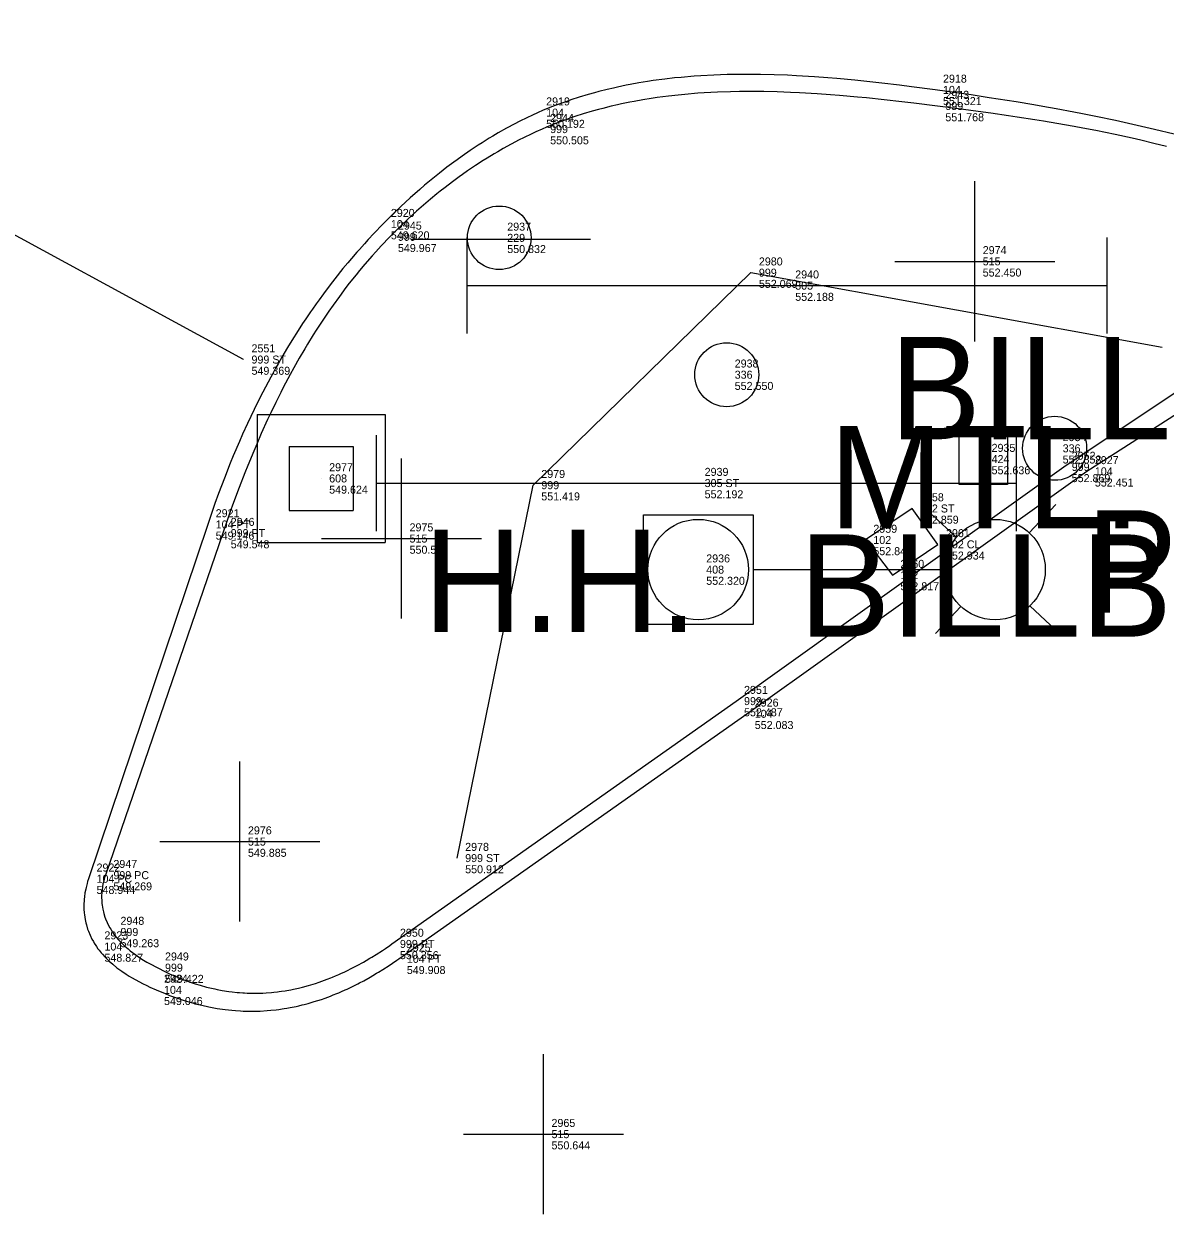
# Model space of a CAD drawing. Extents: x 5447 to 709667, y 4528 to 375505.
# Drawn here: x 708143.16 to 708178.82, y 374179.62 to 374216.81 of the extents above; entities that cross this region are included whole.
import ezdxf

# ---------------------------------------------------------------- set-up
doc = ezdxf.new("R2010")
doc.units = 0
for name, color, linetype in [('SV_BKLN_BKLN', 7, 'Continuous'), ('SV_ILUM_LUMINAIRE_STANDARD', 7, 'Continuous'), ('SV_NODES_ACTIVE_POINT', 7, 'Continuous'), ('SV_NODES_DESCRIPTION', 7, 'Continuous'), ('SV_NODES_ELEVATION', 7, 'Continuous'), ('SV_NODES_PT_NUMBER', 7, 'Continuous'), ('SV_ROAD_BCURB', 7, 'Continuous'), ('SV_ROAD_CONCRD', 7, 'Continuous'), ('SV_SIGN_BB', 7, 'Continuous'), ('SV_SIGN_BB_TX', 7, 'Continuous'), ('SV_SIGN_MISC_SIGN_POST', 7, 'Continuous'), ('SV_SIGN_SIGN', 7, 'Continuous'), ('SV_SIGN_SIGN_TX', 7, 'Continuous'), ('SV_SURF_SPOT', 7, 'Continuous'), ('SV_TRAF_HH', 7, 'Continuous'), ('SV_TRAF_TRAF_TX', 7, 'Continuous'), ('SV_UTOH_MISC_OH', 7, 'Continuous'), ('SV_UTOH_UTOH_TX', 7, 'Continuous')]:
    doc.layers.add(name, color=color, linetype=linetype)

msp = doc.modelspace()

# ---------------------------------------------------------------- linework, layer by layer
at = {"layer": 'SV_BKLN_BKLN'}
for points in [[(708150.021, 374206.324), (708130.411, 374216.99), (708111.595, 374232.817)], [(708178.866, 374212.98), (708178.466, 374213.08), (708178.065, 374213.176), (708177.797, 374213.237), (708177.26, 374213.355), (708176.653, 374213.479), (708176.248, 374213.557), (708175.976, 374213.607), (708175.433, 374213.704), (708175.023, 374213.773), (708174.75, 374213.817), (708174.201, 374213.903), (708173.926, 374213.944), (708173.374, 374214.023), (708172.82, 374214.1), (708172.449, 374214.149), (708171.704, 374214.245), (708170.967, 374214.336), (708170.598, 374214.379), (708170.042, 374214.442), (708169.485, 374214.499), (708169.206, 374214.526), (708168.648, 374214.576), (708168.369, 374214.598), (708167.951, 374214.628), (708167.393, 374214.66), (708167.114, 374214.673), (708166.697, 374214.688), (708166.281, 374214.697), (708166.073, 374214.699), (708165.704, 374214.699), (708165.52, 374214.698), (708165.244, 374214.692), (708164.832, 374214.678), (708164.421, 374214.656), (708164.216, 374214.643), (708163.808, 374214.609), (708163.605, 374214.589), (708163.301, 374214.555), (708162.943, 374214.508), (708162.764, 374214.481), (708162.497, 374214.438), (708162.231, 374214.391), (708162.099, 374214.365), (708161.835, 374214.311), (708161.704, 374214.282), (708161.507, 374214.237), (708161.246, 374214.172), (708161.116, 374214.137), (708160.922, 374214.084), (708160.632, 374213.997), (708160.377, 374213.915), (708160.249, 374213.872), (708160.059, 374213.805), (708159.775, 374213.699), (708159.494, 374213.585), (708159.354, 374213.525), (708159.158, 374213.438), (708159.027, 374213.378), (708158.768, 374213.253), (708158.64, 374213.188), (708158.384, 374213.054), (708158.131, 374212.914), (708157.964, 374212.818), (708157.853, 374212.753), (708157.632, 374212.618), (708157.509, 374212.541), (708157.266, 374212.383), (708157.025, 374212.219), (708156.866, 374212.108), (708156.761, 374212.032), (708156.552, 374211.879), (708156.321, 374211.702), (708156.168, 374211.582), (708156.067, 374211.501), (708155.868, 374211.337), (708155.72, 374211.212), (708155.429, 374210.957), (708155.144, 374210.696), (708154.959, 374210.519), (708154.837, 374210.4), (708154.597, 374210.159), (708154.328, 374209.878), (708154.153, 374209.688), (708154.039, 374209.56), (708153.814, 374209.301), (708153.648, 374209.105), (708153.54, 374208.973), (708153.327, 374208.706), (708153.223, 374208.571), (708153.018, 374208.299), (708152.818, 374208.023), (708152.688, 374207.837), (708152.602, 374207.712), (708152.433, 374207.46), (708152.294, 374207.245), (708152.202, 374207.101), (708152.022, 374206.809), (708151.934, 374206.662), (708151.76, 374206.365), (708151.591, 374206.063), (708151.48, 374205.861), (708151.407, 374205.724), (708151.263, 374205.45), (708151.184, 374205.294), (708151.027, 374204.979), (708150.874, 374204.661), (708150.774, 374204.447), (708150.578, 374204.013), (708150.434, 374203.683), (708150.34, 374203.461), (708150.155, 374203.011), (708150.064, 374202.784), (708149.885, 374202.324), (708149.711, 374201.857), (708149.596, 374201.542), (708149.521, 374201.33), (708149.372, 374200.902), (708145.705, 374190.214), (708145.681, 374190.14), (708145.667, 374190.09), (708145.641, 374189.992), (708145.63, 374189.943), (708145.612, 374189.846), (708145.599, 374189.75), (708145.593, 374189.686), (708145.587, 374189.561), (708145.587, 374189.515), (708145.589, 374189.423), (708145.597, 374189.332), (708145.604, 374189.273), (708145.623, 374189.155), (708145.642, 374189.069), (708145.657, 374189.012), (708145.692, 374188.901), (708145.712, 374188.846), (708145.757, 374188.739), (708145.807, 374188.636), (708145.844, 374188.568), (708145.87, 374188.524), (708145.926, 374188.438), (708145.963, 374188.385), (708146.042, 374188.281), (708146.127, 374188.183), (708146.186, 374188.119), (708146.227, 374188.077), (708146.312, 374187.997), (708146.412, 374187.909), (708146.481, 374187.853), (708146.624, 374187.745), (708146.697, 374187.693), (708146.848, 374187.594), (708147.002, 374187.499), (708147.107, 374187.439), (708147.318, 374187.324), (708147.581, 374187.193), (708147.713, 374187.132), (708147.911, 374187.044), (708148.111, 374186.964), (708148.211, 374186.926), (708148.412, 374186.855), (708148.512, 374186.822), (708148.664, 374186.775), (708148.867, 374186.719), (708148.969, 374186.694), (708149.123, 374186.659), (708149.2, 374186.643), (708149.302, 374186.623), (708149.354, 374186.614), (708149.56, 374186.581), (708149.664, 374186.568), (708149.82, 374186.551), (708149.899, 374186.544), (708150.003, 374186.537), (708150.056, 374186.534), (708150.134, 374186.53), (708150.24, 374186.527), (708150.292, 374186.526), (708150.411, 374186.525), (708150.624, 374186.531), (708150.73, 374186.536), (708150.891, 374186.548), (708150.971, 374186.556), (708151.079, 374186.568), (708151.132, 374186.575), (708151.213, 374186.586), (708151.322, 374186.602), (708151.376, 374186.612), (708151.498, 374186.634), (708151.58, 374186.65), (708151.689, 374186.674), (708151.744, 374186.686), (708151.868, 374186.716), (708152.054, 374186.766), (708152.275, 374186.834), (708152.387, 374186.871), (708152.554, 374186.93), (708152.638, 374186.962), (708152.751, 374187.006), (708152.807, 374187.028), (708152.892, 374187.064), (708153.005, 374187.113), (708153.062, 374187.138), (708153.19, 374187.197), (708153.275, 374187.238), (708153.39, 374187.295), (708153.447, 374187.324), (708153.576, 374187.392), (708153.771, 374187.499), (708153.858, 374187.549), (708153.974, 374187.617), (708154.032, 374187.652), (708154.164, 374187.733), (708154.362, 374187.861), (708154.461, 374187.927), (708154.594, 374188.018), (708154.66, 374188.065), (708165.413, 374195.653), (708175.653, 374202.969), (708179.789, 374205.736)], [(708156.698, 374190.748), (708159.077, 374202.399), (708165.877, 374209.04), (708178.727, 374206.715)]]:
    msp.add_lwpolyline(points, dxfattribs=at)
at = {"layer": 'SV_ILUM_LUMINAIRE_STANDARD'}
for p, q in [((708175.403, 374201.792), (708174.577, 374200.911)), ((708162.518, 374198.048), (708162.518, 374201.474)), ((708162.518, 374201.474), (708165.944, 374201.474)), ((708165.944, 374201.474), (708165.944, 374198.048)), ((708171.544, 374201.474), (708172.303, 374200.769)), ((708165.944, 374199.761), (708171.938, 374199.761)), ((708172.436, 374198.611), (708171.651, 374197.77)), ((708174.596, 374198.63), (708175.566, 374197.723)), ((708165.944, 374198.048), (708162.518, 374198.048))]:
    msp.add_line(p, q, dxfattribs=at)
for centre in [(708164.231, 374199.761), (708173.508, 374199.761)]:
    msp.add_circle(centre, 1.57, dxfattribs=at)
at = {"layer": 'SV_NODES_ACTIVE_POINT'}
for p, q in [((708171.631, 374214.751), (708171.631, 374214.751)), ((708159.229, 374214.04), (708159.229, 374214.04)), ((708171.704, 374214.245), (708171.704, 374214.245)), ((708159.354, 374213.525), (708159.354, 374213.525)), ((708154.376, 374210.556), (708154.376, 374210.556)), ((708154.597, 374210.159), (708154.597, 374210.159)), ((708165.877, 374209.04), (708165.877, 374209.04)), ((708178.727, 374206.715), (708178.727, 374206.715)), ((708150.021, 374206.324), (708150.021, 374206.324)), ((708175.653, 374202.969), (708175.653, 374202.969)), ((708176.375, 374202.832), (708176.375, 374202.832)), ((708159.077, 374202.399), (708159.077, 374202.399)), ((708170.912, 374201.671), (708170.912, 374201.671)), ((708148.902, 374201.173), (708148.902, 374201.173)), ((708149.372, 374200.902), (708149.372, 374200.902)), ((708169.454, 374200.687), (708169.454, 374200.687)), ((708171.724, 374200.55), (708171.724, 374200.55)), ((708170.3, 374199.591), (708170.3, 374199.591)), ((708165.413, 374195.653), (708165.413, 374195.653)), ((708165.748, 374195.255), (708165.748, 374195.255)), ((708156.698, 374190.748), (708156.698, 374190.748)), ((708145.705, 374190.214), (708145.705, 374190.214)), ((708145.179, 374190.102), (708145.179, 374190.102)), ((708145.926, 374188.438), (708145.926, 374188.438)), ((708145.425, 374187.984), (708145.425, 374187.984)), ((708154.66, 374188.065), (708154.66, 374188.065)), ((708154.875, 374187.6), (708154.875, 374187.6)), ((708147.318, 374187.324), (708147.318, 374187.324)), ((708147.287, 374186.631), (708147.287, 374186.631))]:
    msp.add_line(p, q, dxfattribs=at)
at = {"layer": 'SV_ROAD_BCURB'}
msp.add_lwpolyline([(708179.105, 374213.363), (708178.494, 374213.514), (708178.086, 374213.611), (708177.813, 374213.673), (708177.268, 374213.794), (708176.652, 374213.923), (708176.24, 374214.005), (708175.965, 374214.058), (708175.414, 374214.16), (708174.999, 374214.234), (708174.722, 374214.282), (708174.166, 374214.375), (708173.887, 374214.42), (708173.327, 374214.507), (708172.765, 374214.591), (708172.388, 374214.646), (708171.631, 374214.751), (708170.893, 374214.848), (708170.522, 374214.895), (708169.964, 374214.961), (708169.404, 374215.022), (708169.124, 374215.051), (708168.563, 374215.103), (708168.282, 374215.126), (708167.861, 374215.157), (708167.487, 374215.181), (708167.3, 374215.192), (708167.02, 374215.205), (708166.6, 374215.221), (708166.181, 374215.231), (708165.972, 374215.233), (708165.6, 374215.234), (708165.415, 374215.232), (708165.138, 374215.227), (708164.723, 374215.212), (708164.309, 374215.19), (708164.104, 374215.176), (708163.693, 374215.142), (708163.489, 374215.122), (708163.183, 374215.087), (708162.823, 374215.039), (708162.644, 374215.012), (708162.376, 374214.968), (708162.109, 374214.92), (708161.976, 374214.894), (708161.711, 374214.839), (708161.579, 374214.809), (708161.382, 374214.763), (708161.121, 374214.697), (708160.991, 374214.662), (708160.796, 374214.607), (708160.506, 374214.52), (708160.25, 374214.436), (708160.123, 374214.392), (708159.933, 374214.324), (708159.649, 374214.216), (708159.368, 374214.101), (708159.229, 374214.04), (708159.028, 374213.95), (708158.895, 374213.887), (708158.632, 374213.758), (708158.501, 374213.69), (708158.241, 374213.551), (708157.983, 374213.406), (708157.813, 374213.306), (708157.7, 374213.238), (708157.476, 374213.098), (708157.352, 374213.018), (708157.104, 374212.853), (708156.859, 374212.684), (708156.697, 374212.568), (708156.59, 374212.49), (708156.378, 374212.331), (708156.142, 374212.148), (708155.987, 374212.023), (708155.68, 374211.77), (708155.529, 374211.64), (708155.232, 374211.377), (708154.94, 374211.108), (708154.749, 374210.926), (708154.624, 374210.804), (708154.376, 374210.556), (708154.099, 374210.268), (708153.918, 374210.074), (708153.799, 374209.943), (708153.642, 374209.768), (708153.565, 374209.68), (708153.392, 374209.48), (708153.279, 374209.346), (708153.13, 374209.165), (708153.056, 374209.075), (708152.947, 374208.938), (708152.803, 374208.754), (708152.731, 374208.661), (708152.521, 374208.382), (708152.383, 374208.193), (708152.292, 374208.067), (708152.173, 374207.897), (708152.114, 374207.811), (708151.966, 374207.594), (708151.869, 374207.448), (708151.678, 374207.152), (708151.584, 374207.003), (708151.4, 374206.703), (708151.219, 374206.398), (708151.101, 374206.193), (708151.024, 374206.056), (708150.922, 374205.871), (708150.871, 374205.778), (708150.787, 374205.621), (708150.62, 374205.303), (708150.458, 374204.981), (708150.352, 374204.764), (708150.145, 374204.326), (708149.994, 374203.992), (708149.895, 374203.767), (708149.702, 374203.312), (708149.607, 374203.082), (708149.423, 374202.616), (708149.244, 374202.142), (708149.128, 374201.823), (708149.052, 374201.607), (708148.902, 374201.173), (708145.179, 374190.102), (708145.15, 374190.012), (708145.132, 374189.952), (708145.102, 374189.833), (708145.089, 374189.774), (708145.067, 374189.657), (708145.05, 374189.542), (708145.042, 374189.466), (708145.038, 374189.415), (708145.034, 374189.316), (708145.033, 374189.26), (708145.035, 374189.15), (708145.042, 374189.042), (708145.05, 374188.971), (708145.072, 374188.832), (708145.094, 374188.729), (708145.111, 374188.662), (708145.151, 374188.53), (708145.174, 374188.466), (708145.226, 374188.339), (708145.285, 374188.217), (708145.329, 374188.138), (708145.359, 374188.086), (708145.403, 374188.018), (708145.425, 374187.984), (708145.473, 374187.917), (708145.506, 374187.873), (708145.576, 374187.786), (708145.612, 374187.744), (708145.687, 374187.662), (708145.766, 374187.583), (708145.821, 374187.531), (708145.934, 374187.431), (708146.067, 374187.323), (708146.16, 374187.255), (708146.223, 374187.21), (708146.351, 374187.124), (708146.45, 374187.061), (708146.517, 374187.021), (708146.653, 374186.943), (708146.861, 374186.832), (708147.002, 374186.762), (708147.097, 374186.717), (708147.287, 374186.631), (708147.569, 374186.513), (708147.71, 374186.458), (708147.922, 374186.381), (708148.135, 374186.31), (708148.241, 374186.276), (708148.454, 374186.215), (708148.561, 374186.186), (708148.721, 374186.147), (708148.935, 374186.1), (708149.042, 374186.079), (708149.203, 374186.051), (708149.445, 374186.016), (708149.661, 374185.992), (708149.769, 374185.983), (708149.932, 374185.973), (708150.013, 374185.969), (708150.122, 374185.965), (708150.176, 374185.964), (708150.258, 374185.964), (708150.367, 374185.964), (708150.422, 374185.965), (708150.545, 374185.969), (708150.764, 374185.982), (708150.874, 374185.992), (708151.039, 374186.009), (708151.122, 374186.02), (708151.233, 374186.035), (708151.288, 374186.044), (708151.371, 374186.057), (708151.482, 374186.077), (708151.538, 374186.088), (708151.663, 374186.114), (708151.747, 374186.132), (708151.859, 374186.159), (708151.915, 374186.173), (708152.041, 374186.207), (708152.231, 374186.262), (708152.457, 374186.334), (708152.571, 374186.374), (708152.741, 374186.437), (708152.827, 374186.471), (708152.941, 374186.517), (708152.999, 374186.541), (708153.085, 374186.578), (708153.2, 374186.629), (708153.257, 374186.655), (708153.387, 374186.717), (708153.474, 374186.759), (708153.59, 374186.817), (708153.648, 374186.847), (708153.779, 374186.917), (708153.976, 374187.027), (708154.064, 374187.078), (708154.181, 374187.147), (708154.24, 374187.183), (708154.373, 374187.265), (708154.573, 374187.394), (708154.673, 374187.461), (708154.808, 374187.553), (708154.875, 374187.6), (708165.748, 374195.255), (708176.375, 374202.832), (708179.987, 374205.146)], dxfattribs=at)
at = {"layer": 'SV_ROAD_CONCRD'}
msp.add_lwpolyline([(708170.912, 374201.671), (708169.454, 374200.687), (708170.3, 374199.591), (708171.724, 374200.55), (708170.912, 374201.671)], dxfattribs=at)
at = {"layer": 'SV_SIGN_BB'}
for p, q in [((708157.012, 374207.135), (708157.012, 374210.133)), ((708177.012, 374207.135), (708177.012, 374210.133)), ((708157.012, 374208.634), (708177.012, 374208.634)), ((708157.012, 374208.634), (708157.012, 374208.634)), ((708157.012, 374208.634), (708157.012, 374208.634)), ((708154.182, 374200.966), (708154.182, 374203.964)), ((708174.182, 374200.966), (708174.182, 374203.964)), ((708154.182, 374202.465), (708174.182, 374202.465)), ((708154.182, 374202.465), (708154.182, 374202.465)), ((708154.182, 374202.465), (708154.182, 374202.465))]:
    msp.add_line(p, q, dxfattribs=at)
at = {"layer": 'SV_SIGN_MISC_SIGN_POST'}
for centre in [(708165.121, 374205.851), (708175.37, 374203.551)]:
    msp.add_circle(centre, 1, dxfattribs=at)
at = {"layer": 'SV_SIGN_SIGN'}
msp.add_line((708155.267, 374210.083), (708160.863, 374210.083), dxfattribs=at)
msp.add_circle((708158.012, 374210.128), 0.994, dxfattribs=at)
at = {"layer": 'SV_SURF_SPOT'}
for p, q in [((708172.872, 374206.892), (708172.872, 374211.894)), ((708170.371, 374209.393), (708175.373, 374209.393)), ((708172.872, 374209.393), (708172.872, 374209.393)), ((708154.96, 374198.231), (708154.96, 374203.233)), ((708152.459, 374200.732), (708157.461, 374200.732)), ((708154.96, 374200.732), (708154.96, 374200.732)), ((708149.91, 374188.762), (708149.91, 374193.764)), ((708147.409, 374191.263), (708152.411, 374191.263)), ((708149.91, 374191.263), (708149.91, 374191.263)), ((708159.396, 374179.621), (708159.396, 374184.623)), ((708156.895, 374182.122), (708161.897, 374182.122)), ((708159.396, 374182.122), (708159.396, 374182.122))]:
    msp.add_line(p, q, dxfattribs=at)
at = {"layer": 'SV_TRAF_HH'}
for p, q in [((708150.448, 374204.61), (708154.448, 374204.61)), ((708150.448, 374204.61), (708150.448, 374200.61)), ((708154.448, 374204.61), (708154.448, 374200.61)), ((708151.446, 374203.612), (708153.45, 374203.612)), ((708151.446, 374203.612), (708151.446, 374201.608)), ((708153.45, 374203.612), (708153.45, 374201.608)), ((708152.448, 374202.61), (708152.448, 374202.61)), ((708151.446, 374201.608), (708153.45, 374201.608)), ((708150.448, 374200.61), (708154.448, 374200.61))]:
    msp.add_line(p, q, dxfattribs=at)
at = {"layer": 'SV_UTOH_MISC_OH'}
for p, q in [((708172.39, 374202.424), (708172.39, 374203.924)), ((708172.39, 374203.924), (708173.892, 374203.924)), ((708173.892, 374203.924), (708173.892, 374202.424)), ((708173.892, 374202.424), (708172.39, 374202.424))]:
    msp.add_line(p, q, dxfattribs=at)

# ---------------------------------------------------------------- texts
at = {"layer": 'SV_NODES_DESCRIPTION'}
for s, p in [('104', (708171.881, 374214.626)), ('999', (708171.954, 374214.12)), ('104', (708159.479, 374213.915)), ('999', (708159.604, 374213.4)), ('104', (708154.626, 374210.431)), ('999', (708154.847, 374210.034)), ('229', (708158.263, 374210.002)), ('999', (708166.127, 374208.915)), ('515', (708173.122, 374209.268)), ('305', (708167.262, 374208.509)), ('999 ST', (708150.271, 374206.199)), ('336', (708165.371, 374205.726)), ('336', (708175.62, 374203.426)), ('424', (708173.399, 374203.09)), ('999', (708175.903, 374202.844)), ('104', (708176.625, 374202.707)), ('608', (708152.698, 374202.485)), ('999', (708159.327, 374202.274)), ('305 ST', (708164.432, 374202.34)), ('102 ST', (708171.162, 374201.546)), ('104 PT', (708149.152, 374201.048)), ('999 PT', (708149.622, 374200.777)), ('515', (708155.21, 374200.607)), ('102', (708169.704, 374200.562)), ('102 CL', (708171.974, 374200.425)), ('408', (708164.481, 374199.636)), ('102', (708170.55, 374199.466)), ('999', (708165.663, 374195.528)), ('104', (708165.998, 374195.13)), ('515', (708150.16, 374191.138)), ('999 ST', (708156.948, 374190.623)), ('104 PC', (708145.429, 374189.977)), ('999 PC', (708145.955, 374190.089)), ('999', (708146.176, 374188.313)), ('104', (708145.675, 374187.859)), ('999 PT', (708154.91, 374187.94)), ('104 PT', (708155.125, 374187.475)), ('999', (708147.568, 374187.199)), ('104', (708147.537, 374186.506)), ('515', (708159.646, 374181.997))]:
    msp.add_text(s, height=0.25, dxfattribs=at).set_placement(p)
at = {"layer": 'SV_NODES_ELEVATION'}
for s, p in [('551.321', (708171.881, 374214.276)), ('551.768', (708171.954, 374213.77)), ('550.192', (708159.479, 374213.565)), ('550.505', (708159.604, 374213.05)), ('549.620', (708154.626, 374210.081)), ('549.967', (708154.847, 374209.684)), ('550.832', (708158.263, 374209.652)), ('552.450', (708173.122, 374208.918)), ('552.069', (708166.127, 374208.565)), ('552.188', (708167.262, 374208.159)), ('549.369', (708150.271, 374205.849)), ('552.550', (708165.371, 374205.376)), ('552.858', (708175.62, 374203.076)), ('552.636', (708173.399, 374202.74)), ('552.869', (708175.903, 374202.494)), ('552.451', (708176.625, 374202.357)), ('549.624', (708152.698, 374202.135)), ('551.419', (708159.327, 374201.924)), ('552.192', (708164.432, 374201.99)), ('552.859', (708171.162, 374201.196)), ('549.146', (708149.152, 374200.698)), ('549.548', (708149.622, 374200.427)), ('550.590', (708155.21, 374200.257)), ('552.845', (708169.704, 374200.212)), ('552.934', (708171.974, 374200.075)), ('552.320', (708164.481, 374199.286)), ('552.817', (708170.55, 374199.116)), ('552.487', (708165.663, 374195.178)), ('552.083', (708165.998, 374194.78)), ('549.885', (708150.16, 374190.788)), ('550.912', (708156.948, 374190.273)), ('548.944', (708145.429, 374189.627)), ('549.269', (708145.955, 374189.739)), ('549.263', (708146.176, 374187.963)), ('548.827', (708145.675, 374187.509)), ('550.356', (708154.91, 374187.59)), ('549.908', (708155.125, 374187.125)), ('549.422', (708147.568, 374186.849)), ('549.046', (708147.537, 374186.156)), ('550.644', (708159.646, 374181.647))]:
    msp.add_text(s, height=0.25, dxfattribs=at).set_placement(p)
at = {"layer": 'SV_NODES_PT_NUMBER'}
for s, p in [('2918', (708171.881, 374214.976)), ('2919', (708159.479, 374214.265)), ('2943', (708171.954, 374214.47)), ('2944', (708159.604, 374213.75)), ('2920', (708154.626, 374210.781)), ('2945', (708154.847, 374210.384)), ('2937', (708158.263, 374210.352)), ('2974', (708173.122, 374209.618)), ('2980', (708166.127, 374209.265)), ('2940', (708167.262, 374208.859)), ('2551', (708150.271, 374206.549)), ('2938', (708165.371, 374206.076)), ('2934', (708175.62, 374203.776)), ('2935', (708173.399, 374203.44)), ('2952', (708175.903, 374203.194)), ('2927', (708176.625, 374203.057)), ('2977', (708152.698, 374202.835)), ('2979', (708159.327, 374202.624)), ('2939', (708164.432, 374202.69)), ('2958', (708171.162, 374201.896)), ('2921', (708149.152, 374201.398)), ('2946', (708149.622, 374201.127)), ('2975', (708155.21, 374200.957)), ('2959', (708169.704, 374200.912)), ('2961', (708171.974, 374200.775)), ('2936', (708164.481, 374199.986)), ('2960', (708170.55, 374199.816)), ('2951', (708165.663, 374195.878)), ('2926', (708165.998, 374195.48)), ('2976', (708150.16, 374191.488)), ('2978', (708156.948, 374190.973)), ('2922', (708145.429, 374190.327)), ('2947', (708145.955, 374190.439)), ('2948', (708146.176, 374188.663)), ('2923', (708145.675, 374188.209)), ('2950', (708154.91, 374188.29)), ('2925', (708155.125, 374187.825)), ('2949', (708147.568, 374187.549)), ('2924', (708147.537, 374186.856)), ('2965', (708159.646, 374182.347))]:
    msp.add_text(s, height=0.25, dxfattribs=at).set_placement(p)
at = {"layer": 'SV_SIGN_BB_TX'}
for p in [(708170.212, 374203.834), (708167.382, 374197.665)]:
    msp.add_text('BILLBOARD', height=3.2, dxfattribs=at).set_placement(p)
at = {"layer": 'SV_SIGN_SIGN_TX'}
msp.add_text('MTL. POST', height=3.2, dxfattribs=at).set_placement((708168.321, 374201.051))
at = {"layer": 'SV_TRAF_TRAF_TX'}
msp.add_text('H.H.', height=3.2, dxfattribs=at).set_placement((708155.648, 374197.81))
at = {"layer": 'SV_UTOH_UTOH_TX'}
msp.add_text('PAY PHONE', height=3.2, dxfattribs=at).set_placement((708176.349, 374198.415))

doc.saveas('drawing.dxf')
